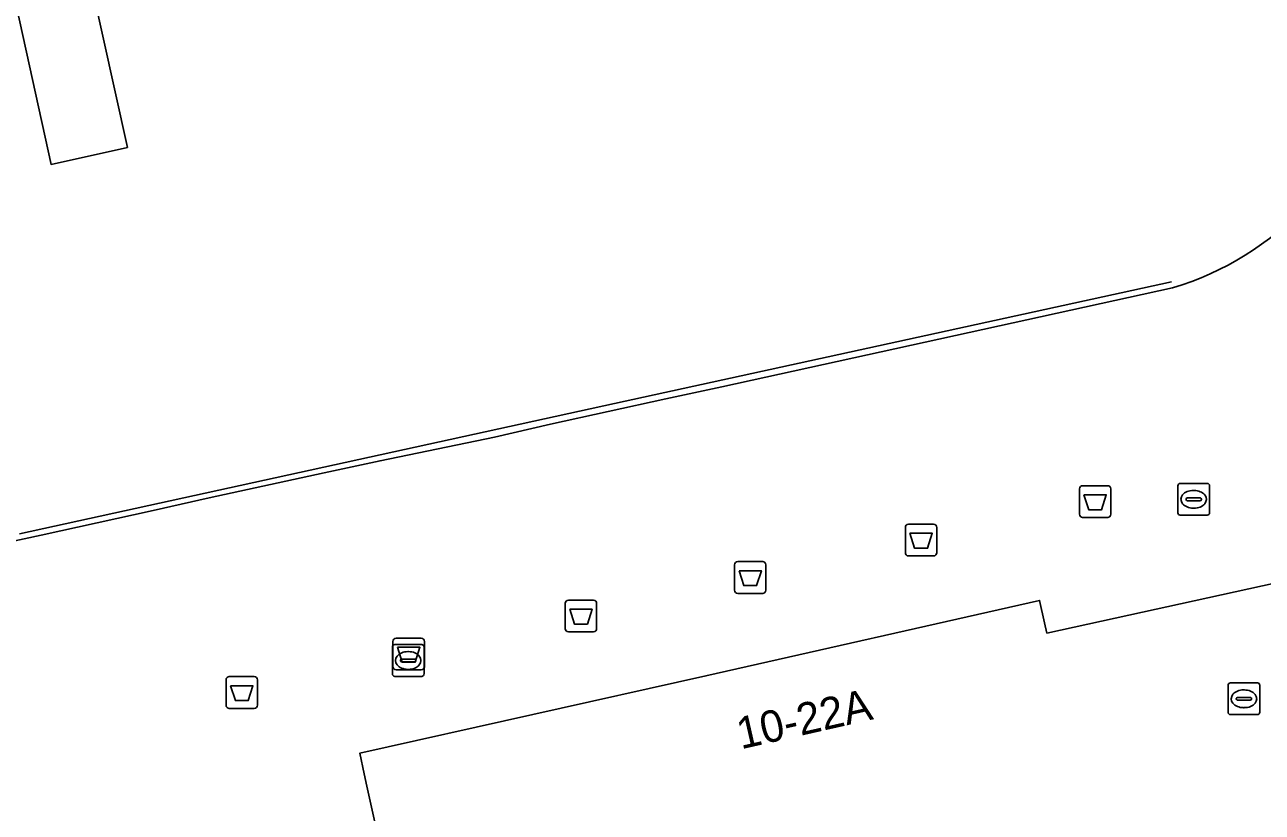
# Model space of a CAD drawing. Extents: x 160806 to 161707, y 383696 to 384148.
# Drawn here: x 161358.71 to 161397.72, y 383824.29 to 383849.13 of the extents above; entities that cross this region are included whole.
import ezdxf

# ---------------------------------------------------------------- set-up
doc = ezdxf.new("R2010")
doc.units = 0
for name, color, linetype in [('IMGEO_Afvalbak', 7, 'Continuous'), ('IMGEO_Brandkraan', 7, 'Continuous'), ('IMGEO_Kolk', 7, 'Continuous'), ('IMGEO_Lijnafwatering', 7, 'Continuous'), ('IMGEO_OVBaan_gesloten', 7, 'Continuous'), ('IMGEO_Pand', 7, 'Continuous'), ('IMGEO_Pand_nummerreeks', 7, 'Continuous'), ('IMGEO_Rioolput', 7, 'Continuous'), ('IMGEO_Verkeerseiland_open', 7, 'Continuous'), ('IMGEO_Voetgangersgebied_open', 7, 'Continuous')]:
    doc.layers.add(name, color=color, linetype=linetype)

msp = doc.modelspace()

# ---------------------------------------------------------------- linework, layer by layer
at = {"layer": 'IMGEO_Afvalbak'}
for p, q in [((161392.061, 383834.592), (161392.851, 383834.592)), ((161392.851, 383834.592), (161392.061, 383834.592)), ((161391.961, 383833.692), (161391.961, 383834.492)), ((161391.961, 383834.492), (161391.961, 383833.692)), ((161392.951, 383834.492), (161392.951, 383833.692)), ((161392.951, 383833.692), (161392.951, 383834.492)), ((161386.573, 383833.378), (161387.363, 383833.378)), ((161387.363, 383833.378), (161386.573, 383833.378)), ((161392.851, 383833.592), (161392.061, 383833.592)), ((161392.061, 383833.592), (161392.851, 383833.592)), ((161386.473, 383832.478), (161386.473, 383833.278)), ((161386.473, 383833.278), (161386.473, 383832.478)), ((161387.463, 383833.278), (161387.463, 383832.478)), ((161387.463, 383832.478), (161387.463, 383833.278)), ((161381.186, 383832.197), (161381.976, 383832.197)), ((161381.976, 383832.197), (161381.186, 383832.197)), ((161387.363, 383832.378), (161386.573, 383832.378)), ((161386.573, 383832.378), (161387.363, 383832.378)), ((161381.086, 383831.297), (161381.086, 383832.097)), ((161381.086, 383832.097), (161381.086, 383831.297)), ((161382.076, 383832.097), (161382.076, 383831.297)), ((161382.076, 383831.297), (161382.076, 383832.097)), ((161381.976, 383831.197), (161381.186, 383831.197)), ((161381.186, 383831.197), (161381.976, 383831.197)), ((161375.748, 383830.083), (161375.748, 383830.883)), ((161375.748, 383830.883), (161375.748, 383830.083)), ((161375.848, 383830.983), (161376.638, 383830.983)), ((161376.638, 383830.983), (161375.848, 383830.983)), ((161376.738, 383830.883), (161376.738, 383830.083)), ((161376.738, 383830.083), (161376.738, 383830.883)), ((161376.638, 383829.983), (161375.848, 383829.983)), ((161375.848, 383829.983), (161376.638, 383829.983)), ((161370.318, 383828.883), (161370.318, 383829.683)), ((161370.318, 383829.683), (161370.318, 383828.883)), ((161370.418, 383829.783), (161371.208, 383829.783)), ((161371.208, 383829.783), (161370.418, 383829.783)), ((161371.308, 383829.683), (161371.308, 383828.883)), ((161371.308, 383828.883), (161371.308, 383829.683)), ((161371.208, 383828.783), (161370.418, 383828.783)), ((161370.418, 383828.783), (161371.208, 383828.783)), ((161365.056, 383827.67), (161365.056, 383828.47)), ((161365.056, 383828.47), (161365.056, 383827.67)), ((161365.156, 383828.57), (161365.946, 383828.57)), ((161365.946, 383828.57), (161365.156, 383828.57)), ((161366.046, 383828.47), (161366.046, 383827.67)), ((161366.046, 383827.67), (161366.046, 383828.47)), ((161365.946, 383827.57), (161365.156, 383827.57)), ((161365.156, 383827.57), (161365.946, 383827.57))]:
    msp.add_line(p, q, dxfattribs=at)
for points in [[(161392.104, 383834.306), (161392.808, 383834.306), (161392.659, 383833.836), (161392.253, 383833.836), (161392.104, 383834.306)], [(161386.616, 383833.092), (161387.32, 383833.092), (161387.171, 383832.622), (161386.765, 383832.622), (161386.616, 383833.092)], [(161381.229, 383831.911), (161381.933, 383831.911), (161381.784, 383831.441), (161381.378, 383831.441), (161381.229, 383831.911)], [(161375.891, 383830.697), (161376.595, 383830.697), (161376.446, 383830.227), (161376.04, 383830.227), (161375.891, 383830.697)], [(161370.461, 383829.497), (161371.165, 383829.497), (161371.016, 383829.027), (161370.61, 383829.027), (161370.461, 383829.497)], [(161365.199, 383828.284), (161365.903, 383828.284), (161365.754, 383827.814), (161365.348, 383827.814), (161365.199, 383828.284)]]:
    msp.add_lwpolyline(points, dxfattribs=at)
for centre, start, end in [((161392.061, 383834.492), 90, 180), ((161392.061, 383834.492), 90, 180), ((161392.851, 383834.492), 0, 90), ((161392.851, 383834.492), 360, 90), ((161386.573, 383833.278), 90, 180), ((161386.573, 383833.278), 90, 180), ((161387.363, 383833.278), 0, 90), ((161387.363, 383833.278), 360, 90), ((161392.061, 383833.692), 180, 270), ((161392.061, 383833.692), 180, 270), ((161392.851, 383833.692), 270, 0), ((161392.851, 383833.692), 270, 0), ((161381.186, 383832.097), 90, 180), ((161381.186, 383832.097), 90, 180), ((161381.976, 383832.097), 0, 90), ((161381.976, 383832.097), 360, 90), ((161386.573, 383832.478), 180, 270), ((161386.573, 383832.478), 180, 270), ((161387.363, 383832.478), 270, 0), ((161387.363, 383832.478), 270, 0), ((161381.186, 383831.297), 180, 270), ((161381.186, 383831.297), 180, 270), ((161381.976, 383831.297), 270, 0), ((161381.976, 383831.297), 270, 0), ((161375.848, 383830.883), 90, 180), ((161375.848, 383830.883), 90, 180), ((161376.638, 383830.883), 0, 90), ((161376.638, 383830.883), 360, 90), ((161375.848, 383830.083), 180, 270), ((161375.848, 383830.083), 180, 270), ((161376.638, 383830.083), 270, 0), ((161376.638, 383830.083), 270, 0), ((161370.418, 383829.683), 90, 180), ((161370.418, 383829.683), 90, 180), ((161371.208, 383829.683), 0, 90), ((161371.208, 383829.683), 360, 90), ((161370.418, 383828.883), 180, 270), ((161370.418, 383828.883), 180, 270), ((161371.208, 383828.883), 270, 0), ((161371.208, 383828.883), 270, 0), ((161365.156, 383828.47), 90, 180), ((161365.156, 383828.47), 90, 180), ((161365.946, 383828.47), 0, 90), ((161365.946, 383828.47), 360, 90), ((161365.156, 383827.67), 180, 270), ((161365.156, 383827.67), 180, 270), ((161365.946, 383827.67), 270, 0), ((161365.946, 383827.67), 270, 0)]:
    msp.add_arc(centre, 0.1, start, end, dxfattribs=at)
at = {"layer": 'IMGEO_Brandkraan'}
for p, q in [((161396.647, 383827.446), (161396.647, 383828.298)), ((161396.722, 383828.372), (161397.574, 383828.372)), ((161397.648, 383828.298), (161397.648, 383827.446)), ((161396.906, 383827.866), (161396.906, 383827.878)), ((161396.949, 383827.915), (161397.347, 383827.915)), ((161397.135, 383828.152), (161397.16, 383828.152)), ((161397.39, 383827.878), (161397.39, 383827.866)), ((161397.344, 383827.829), (161396.946, 383827.829)), ((161397.158, 383827.592), (161397.133, 383827.592)), ((161397.574, 383827.372), (161396.722, 383827.372))]:
    msp.add_line(p, q, dxfattribs=at)
for points in [[(161396.647, 383827.446), (161396.647, 383828.298)], [(161396.722, 383828.372), (161397.574, 383828.372)], [(161397.648, 383828.298), (161397.648, 383827.446)], [(161397.574, 383827.372), (161396.722, 383827.372)]]:
    msp.add_lwpolyline(points, dxfattribs=at)
for centre, radius, start, end in [((161396.724, 383828.296), 0.0765, 91.552, 178.448), ((161396.724, 383828.296), 0.0765, 91.552, 178.448), ((161397.572, 383828.296), 0.0765, 1.552, 88.448), ((161397.572, 383828.296), 0.0765, 1.552, 88.448), ((161396.946, 383827.875), 0.0403, 85.8775, 175.7526), ((161397.351, 383827.877), 0.0386, 1.7309, 96.639), ((161396.943, 383827.865), 0.0366, 178.938, 274.7102), ((161397.347, 383827.872), 0.043, 264.8664, 352.4533), ((161396.724, 383827.448), 0.0765, 181.552, 268.448), ((161396.724, 383827.448), 0.0765, 181.552, 268.448), ((161397.572, 383827.448), 0.0765, 271.552, 358.448), ((161397.572, 383827.448), 0.0765, 271.552, 358.448)]:
    msp.add_arc(centre, radius, start, end, dxfattribs=at)
for centre, major_axis, ratio, start_param, end_param in [((161397.134, 383827.872), (-0.387, 0.002), 0.722429, 4.712389, 7.853982), ((161397.159, 383827.872), (-0.39, 0.002), 0.717154, 1.570796, 4.712389)]:
    msp.add_ellipse(centre, major_axis=major_axis, ratio=ratio, start_param=start_param, end_param=end_param, dxfattribs=at)
at = {"layer": 'IMGEO_Kolk'}
for p, q in [((161395.062, 383833.737), (161395.062, 383834.589)), ((161395.137, 383834.663), (161395.989, 383834.663)), ((161396.063, 383834.589), (161396.063, 383833.737)), ((161395.321, 383834.157), (161395.321, 383834.169)), ((161395.759, 383834.12), (161395.361, 383834.12)), ((161395.364, 383834.206), (161395.762, 383834.206)), ((161395.55, 383834.443), (161395.575, 383834.443)), ((161395.805, 383834.169), (161395.805, 383834.157)), ((161395.573, 383833.883), (161395.548, 383833.883)), ((161395.989, 383833.663), (161395.137, 383833.663))]:
    msp.add_line(p, q, dxfattribs=at)
for points in [[(161395.062, 383833.737), (161395.062, 383834.589)], [(161395.137, 383834.663), (161395.989, 383834.663)], [(161396.063, 383834.589), (161396.063, 383833.737)], [(161395.989, 383833.663), (161395.137, 383833.663)]]:
    msp.add_lwpolyline(points, dxfattribs=at)
for centre, radius, start, end in [((161395.139, 383834.587), 0.0765, 91.552, 178.448), ((161395.139, 383834.587), 0.0765, 91.552, 178.448), ((161395.987, 383834.587), 0.0765, 1.552, 88.448), ((161395.987, 383834.587), 0.0765, 1.552, 88.448), ((161395.361, 383834.166), 0.0403, 85.8775, 175.7526), ((161395.358, 383834.156), 0.0366, 178.938, 274.7102), ((161395.762, 383834.163), 0.043, 264.8664, 352.4533), ((161395.766, 383834.168), 0.0386, 1.7309, 96.639), ((161395.139, 383833.739), 0.0765, 181.552, 268.448), ((161395.139, 383833.739), 0.0765, 181.552, 268.448), ((161395.987, 383833.739), 0.0765, 271.552, 358.448), ((161395.987, 383833.739), 0.0765, 271.552, 358.448)]:
    msp.add_arc(centre, radius, start, end, dxfattribs=at)
for centre, major_axis, ratio, start_param, end_param in [((161395.549, 383834.163), (-0.387, 0.002), 0.722429, 4.712389, 7.853982), ((161395.574, 383834.163), (-0.39, 0.002), 0.717154, 1.570796, 4.712389)]:
    msp.add_ellipse(centre, major_axis=major_axis, ratio=ratio, start_param=start_param, end_param=end_param, dxfattribs=at)
at = {"layer": 'IMGEO_Lijnafwatering'}
for points in [[(161394.865, 383841.025), (161377.297, 383837.18)], [(161377.297, 383837.18), (161358.544, 383833.075)]]:
    msp.add_lwpolyline(points, dxfattribs=at)
at = {"layer": 'IMGEO_OVBaan_gesloten'}
msp.add_lwpolyline([(161361.943, 383845.257), (161359.538, 383844.727), (161356.872, 383856.844), (161353.857, 383870.541), (161356.239, 383871.076), (161359.267, 383857.372)], close=True, dxfattribs=at)
msp.add_lwpolyline([(161317.419, 383834.272), (161320.903, 383833.041), (161325.598, 383831.395), (161335.734, 383827.866), (161337.61, 383828.281), (161341.551, 383829.169), (161343.322, 383829.562), (161346.737, 383830.315), (161348.495, 383830.684), (161352.057, 383831.466), (161353.825, 383831.84), (161357.457, 383832.655), (161359.221, 383833.037), (161362.756, 383833.811), (161364.52, 383834.206), (161368.15, 383835.002), (161369.909, 383835.381), (161373.519, 383836.126), (161375.28, 383836.529), (161378.924, 383837.328), (161380.683, 383837.71), (161394.899, 383840.828)], dxfattribs=at)
msp.add_arc((161392.082, 383850.105), 9.695, 286.8908, 345.9254, dxfattribs=at)
at = {"layer": 'IMGEO_Pand'}
msp.add_lwpolyline([(161405.826, 383833.211), (161390.937, 383829.942), (161390.863, 383830.269), (161390.704, 383830.974), (161380.182, 383828.591), (161369.268, 383826.155), (161369.411, 383825.503), (161369.496, 383825.119), (161370.039, 383822.657), (161342.321, 383816.504)], dxfattribs=at)
at = {"layer": 'IMGEO_Rioolput'}
for p, q in [((161370.298, 383828.654), (161370.298, 383829.506)), ((161370.373, 383829.58), (161371.225, 383829.58)), ((161371.299, 383829.506), (161371.299, 383828.654)), ((161370.557, 383829.074), (161370.557, 383829.086)), ((161370.6, 383829.123), (161370.998, 383829.123)), ((161370.786, 383829.36), (161370.811, 383829.36)), ((161371.041, 383829.086), (161371.041, 383829.074)), ((161370.995, 383829.037), (161370.597, 383829.037)), ((161370.809, 383828.8), (161370.784, 383828.8)), ((161371.225, 383828.58), (161370.373, 383828.58))]:
    msp.add_line(p, q, dxfattribs=at)
for points in [[(161370.298, 383828.654), (161370.298, 383829.506)], [(161370.373, 383829.58), (161371.225, 383829.58)], [(161371.299, 383829.506), (161371.299, 383828.654)], [(161371.225, 383828.58), (161370.373, 383828.58)]]:
    msp.add_lwpolyline(points, dxfattribs=at)
for centre, radius, start, end in [((161370.375, 383829.504), 0.0765, 91.552, 178.448), ((161370.375, 383829.504), 0.0765, 91.552, 178.448), ((161371.223, 383829.504), 0.0765, 1.552, 88.448), ((161371.223, 383829.504), 0.0765, 1.552, 88.448), ((161370.597, 383829.083), 0.0403, 85.8775, 175.7526), ((161370.594, 383829.073), 0.0366, 178.938, 274.7102), ((161370.998, 383829.08), 0.043, 264.8664, 352.4533), ((161371.002, 383829.085), 0.0386, 1.7309, 96.639), ((161370.375, 383828.656), 0.0765, 181.552, 268.448), ((161370.375, 383828.656), 0.0765, 181.552, 268.448), ((161371.223, 383828.656), 0.0765, 271.552, 358.448), ((161371.223, 383828.656), 0.0765, 271.552, 358.448)]:
    msp.add_arc(centre, radius, start, end, dxfattribs=at)
for centre, major_axis, ratio, start_param, end_param in [((161370.785, 383829.08), (-0.387, 0.002), 0.722429, 4.712389, 7.853982), ((161370.81, 383829.08), (-0.39, 0.002), 0.717154, 1.570796, 4.712389)]:
    msp.add_ellipse(centre, major_axis=major_axis, ratio=ratio, start_param=start_param, end_param=end_param, dxfattribs=at)
at = {"layer": 'IMGEO_Verkeerseiland_open'}
msp.add_lwpolyline([(161361.943, 383845.257), (161359.267, 383857.372), (161356.239, 383871.076), (161353.857, 383870.541), (161356.872, 383856.844), (161359.538, 383844.727)], close=True, dxfattribs=at)
at = {"layer": 'IMGEO_Voetgangersgebied_open'}
for points in [[(161390.704, 383830.974), (161390.863, 383830.269), (161390.937, 383829.942), (161405.826, 383833.211), (161405.74, 383833.578), (161426.148, 383838.123), (161419.198, 383841.931), (161418.448, 383842.342), (161411.478, 383846.162), (161403.061, 383863.005)], [(161394.899, 383840.828), (161380.683, 383837.71), (161378.924, 383837.328), (161375.28, 383836.529), (161373.519, 383836.126), (161369.909, 383835.381), (161368.15, 383835.002), (161364.52, 383834.206), (161362.756, 383833.811), (161359.221, 383833.037), (161357.457, 383832.655), (161353.825, 383831.84), (161352.057, 383831.466), (161348.495, 383830.684), (161346.737, 383830.315), (161343.322, 383829.562), (161341.551, 383829.169), (161337.61, 383828.281), (161335.734, 383827.866), (161325.598, 383831.395), (161320.903, 383833.041)], [(161342.321, 383816.504), (161370.039, 383822.657), (161369.496, 383825.119), (161369.411, 383825.503), (161369.268, 383826.155), (161380.182, 383828.591), (161390.704, 383830.974)]]:
    msp.add_lwpolyline(points, dxfattribs=at)
msp.add_arc((161392.082, 383850.105), 9.695, 286.8908, 345.9254, dxfattribs=at)

# ---------------------------------------------------------------- texts
at = {"layer": 'IMGEO_Pand_nummerreeks'}
msp.add_text('10-22A', height=1, rotation=12.7999, dxfattribs=at).set_placement((161381.287, 383826.276))

doc.saveas('drawing.dxf')
